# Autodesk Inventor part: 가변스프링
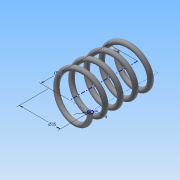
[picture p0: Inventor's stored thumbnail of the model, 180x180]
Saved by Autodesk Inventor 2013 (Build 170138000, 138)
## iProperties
Created: 2015-03
Part Number: 가변스프링
Material: 강철, 탄소
Document SubType Name: Modeling
Designer: Administrator
Density: 7.87 g/cm^3
Mass: 48.2733 g
Surface Area: 62.0009 cm^2
Volume: 6.13384 cm^3
Author: Administrator
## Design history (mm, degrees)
sketch "스케치1"
  geometry: L1 (0, 0)-(17.5, 0); L2 (17.5, 0)-(17.5, 43.5); L3 (17.5, 43.5)-(0, 43.5); L4 (0, 43.5)-(0, 0); C1 r 2 at (17.5, 0)
  constraints: 8 end point, 2 parallel, 1 centre point, 1 coincident, 1 horizontal, 1 perpendicular
  dimensions: "d0" = 43.5 distance of L3.end L1.start (derived); "d1" = 35 diameter of L2 L4; "d2" = 4 diameter of C1
feature "코일1" sketch "스케치1" pitch "d3" = 10; turns "d5" = 4.5; dims "d4" = 43.5 (= d0), "d6" = 0, angle "d7" = 90 deg, angle "d8" = 90 deg, "d9" = 0, "d10" = 0
sketch "스케치2"
  geometry: L1 (-19.5, 0)-(-15.5, 0) reference; 1 further point
  constraints: 1 horizontal alignment
extrude "돌출1" cut sketch "스케치2" stored distance "d11" = 10; taper "d12" = 0 deg
node "작업 평면1"
sketch "스케치3"
  geometry: L1 (-19.5, 0)-(-15.5, 0) reference; 1 further point
  constraints: 1 horizontal alignment
extrude "돌출2" cut sketch "스케치3" stored distance "d14" = 10; taper "d15" = 0 deg
node "솔리드1"
node "절단 모서리 투영1"
node "절단 모서리 투영2"
other parameters: "d13" = -43.5 (= -d0)
